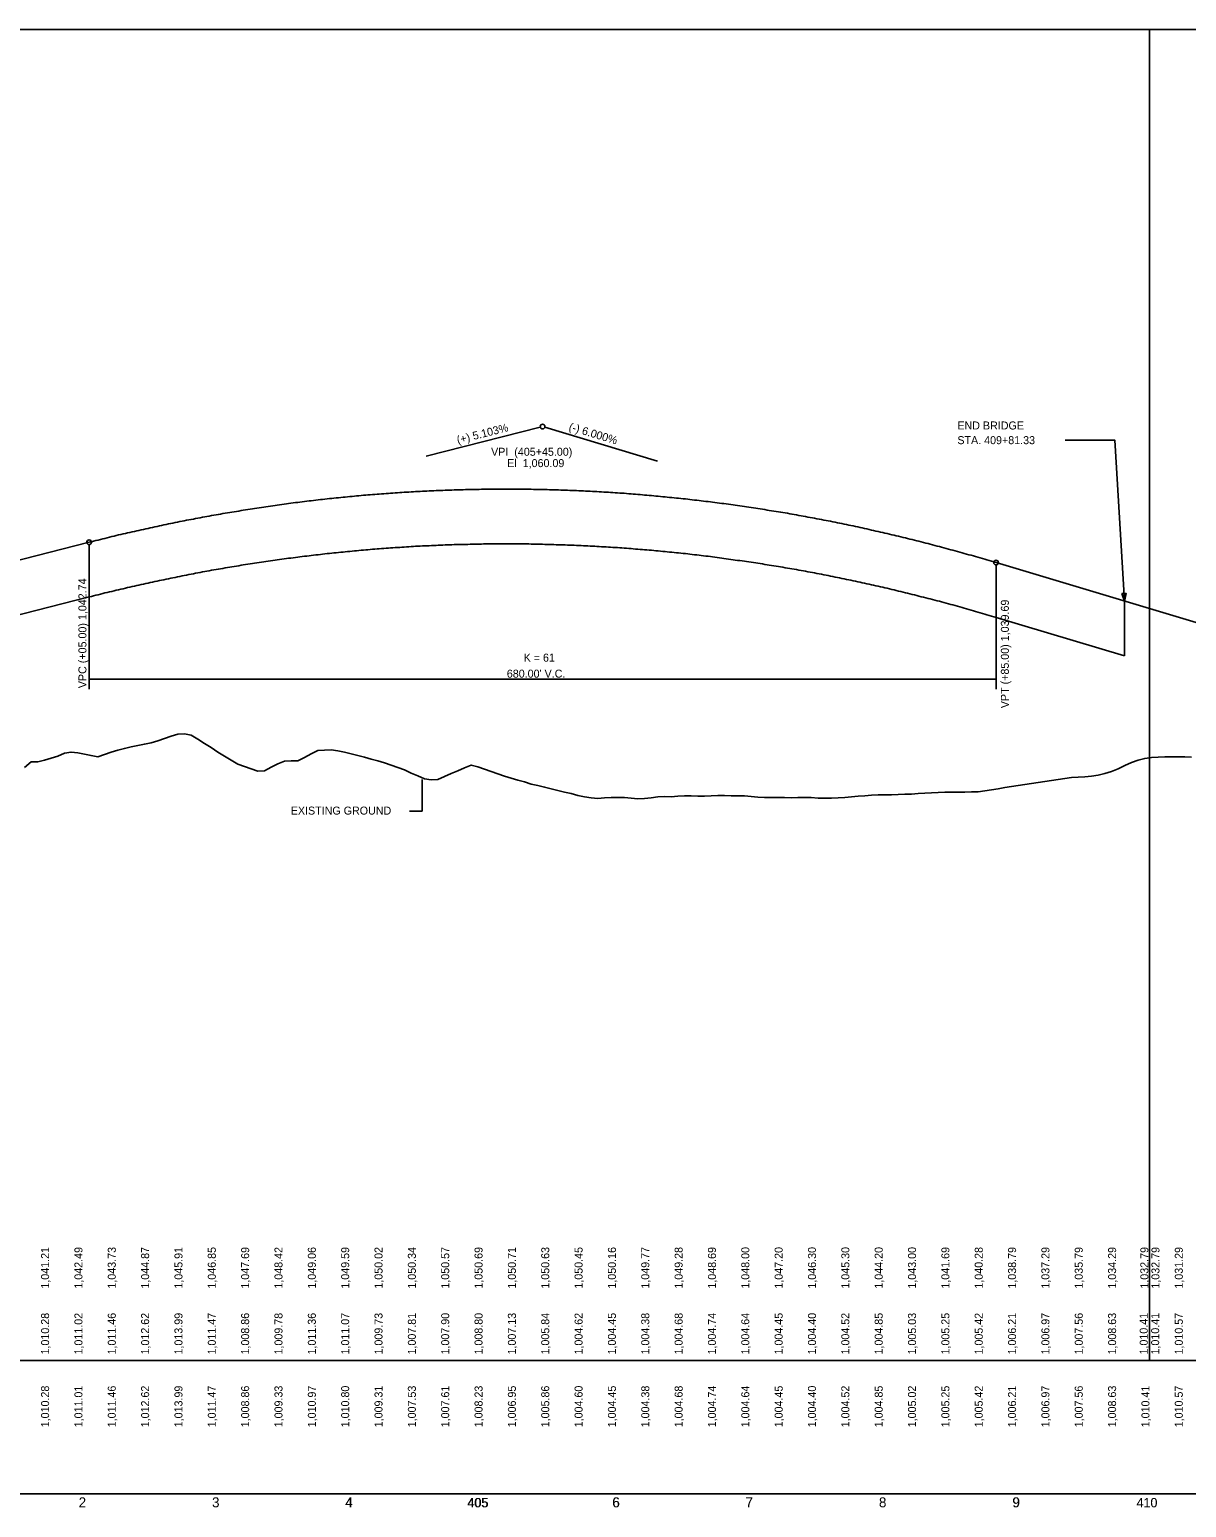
# Model space of a CAD drawing. Extents: x 150 to 16976893, y 3102 to 12559827.
# Drawn here: x 16974553 to 16975421, y 12558429 to 12559538 of the extents above; entities that cross this region are included whole.
import ezdxf

# ---------------------------------------------------------------- set-up
doc = ezdxf.new("R2010")
doc.units = 0
for name, color, linetype in [('Default', 7, 'Continuous'), ('Level 56', 7, 'Continuous'), ('RD_DDB_Ex_Tx', 7, 'Continuous'), ('RD_DDB_GradeTX', 7, 'Continuous'), ('RD_DDB_PI', 7, 'Continuous'), ('RD_DDB_Profile_EX', 7, 'Continuous'), ('RD_DDB_StaTX', 7, 'Continuous'), ('RD_DDB_StripGrade_EX', 7, 'Continuous'), ('RD_GPK_Profile_Cell', 7, 'Continuous'), ('RD_HC_TX_Sta20', 7, 'Continuous'), ('RD_PD_Bridge', 7, 'Continuous'), ('RD_PD_PatLn_I85', 7, 'Continuous'), ('RD_XS_Misc_Line', 7, 'Continuous')]:
    doc.layers.add(name, color=color, linetype=linetype)

msp = doc.modelspace()

# ---------------------------------------------------------------- linework, layer by layer
at = {"layer": 'Default'}
for points in [[(16973892.9, 12558539.3), (16975392.9, 12558539.3), (16975392.9, 12559537.5), (16973892.9, 12559537.5)], [(16975392.9, 12558539.3), (16976892.9, 12558539.3), (16976892.9, 12559537.5), (16975392.9, 12559537.5)]]:
    msp.add_lwpolyline(points, close=True, dxfattribs=at)
at = {"layer": 'RD_DDB_Ex_Tx'}
for p, q in [((16974847.7, 12558951.3), (16974847.7, 12558975.2)), ((16974838, 12558951.3), (16974847.7, 12558951.3))]:
    msp.add_line(p, q, dxfattribs=at)
at = {"layer": 'RD_DDB_PI'}
for p, q in [((16974850.7, 12559217.5), (16974936.2, 12559239.3)), ((16975024.1, 12559213.9), (16974939.6, 12559239.3))]:
    msp.add_line(p, q, dxfattribs=at)
msp.add_circle((16974937.9, 12559239.8), 1.75, dxfattribs=at)
at = {"layer": 'RD_DDB_Profile_EX'}
for points in [[(16974549.4, 12558984.1), (16974554.4, 12558988.4), (16974559.4, 12558988.3), (16974564.4, 12558989.7), (16974569.4, 12558991.1), (16974574.4, 12558992.7), (16974579.4, 12558994.8), (16974584.4, 12558995.7), (16974589.4, 12558995), (16974594.4, 12558994.2), (16974599.4, 12558993.1), (16974604.4, 12558992.2), (16974609.4, 12558993.9), (16974614.4, 12558995.6), (16974619.4, 12558997), (16974624.4, 12558998.4), (16974629.4, 12558999.5), (16974634.4, 12559000.6), (16974639.4, 12559001.7), (16974644.4, 12559002.7), (16974649.4, 12559004.2), (16974654.4, 12559005.9), (16974659.4, 12559007.6), (16974664.4, 12559009.1), (16974669.4, 12559009.3), (16974674.4, 12559008.3), (16974679.4, 12559005.4), (16974684.4, 12559002.2), (16974689.4, 12558999), (16974694.4, 12558995.7), (16974699.4, 12558992.6), (16974704.4, 12558989.5), (16974709.4, 12558986.5), (16974714.4, 12558984.9), (16974719.4, 12558983.1), (16974724.4, 12558981.4), (16974729.4, 12558981.7), (16974734.4, 12558984.3), (16974739.4, 12558986.8), (16974744.4, 12558988.8), (16974749.4, 12558989), (16974754.4, 12558989), (16974759.4, 12558991.6)], [(16974759.4, 12558991.6), (16974764.4, 12558994.3), (16974769.4, 12558996.8), (16974774.4, 12558997.2), (16974779.4, 12558997.3), (16974784.4, 12558996.6), (16974789.4, 12558995.5), (16974794.4, 12558994.3), (16974799.4, 12558993.1), (16974804.4, 12558991.8), (16974809.4, 12558990.4), (16974814.4, 12558989), (16974819.4, 12558987.5), (16974824.4, 12558985.8), (16974829.4, 12558984.2), (16974834.4, 12558982.4), (16974839.4, 12558979.8), (16974844.4, 12558977.8), (16974849.4, 12558975.7), (16974854.4, 12558974.8), (16974859.4, 12558975.1), (16974864.4, 12558977.3), (16974869.4, 12558979.5), (16974874.4, 12558981.6), (16974879.4, 12558983.8), (16974884.4, 12558985.9), (16974889.4, 12558984.5), (16974894.4, 12558982.8), (16974899.4, 12558981.1), (16974904.4, 12558979.4), (16974909.4, 12558977.7), (16974914.4, 12558976), (16974919.4, 12558974.5), (16974924.4, 12558973.3), (16974929.4, 12558971.5), (16974934.4, 12558970.5), (16974939.4, 12558969.4), (16974944.4, 12558968.1), (16974949.4, 12558966.9), (16974954.4, 12558965.7), (16974959.4, 12558964.5), (16974964.4, 12558963.1), (16974969.4, 12558962.1), (16974974.4, 12558961.4), (16974979.4, 12558960.9), (16974984.4, 12558961.3), (16974989.4, 12558961.6), (16974994.4, 12558961.5), (16974999.4, 12558961.6), (16975004.4, 12558961), (16975009.4, 12558960.7), (16975014.4, 12558960.9), (16975019.4, 12558961.3), (16975024.4, 12558962), (16975029.4, 12558962.4), (16975034.4, 12558962.2), (16975039.4, 12558962.5), (16975044.4, 12558962.8), (16975049.4, 12558962.8), (16975054.4, 12558962.6), (16975059.4, 12558962.6), (16975064.4, 12558962.8), (16975069.4, 12558963.1), (16975074.4, 12558963), (16975079.4, 12558962.9), (16975084.4, 12558962.9), (16975089.4, 12558962.8), (16975094.4, 12558962.4), (16975099.4, 12558961.9), (16975104.4, 12558961.6), (16975109.4, 12558961.6), (16975114.4, 12558961.7), (16975119.4, 12558961.5), (16975124.4, 12558961.4), (16975129.4, 12558961.5), (16975134.4, 12558961.6), (16975139.4, 12558961.5), (16975144.4, 12558961.2), (16975149.4, 12558961), (16975154.4, 12558961.1), (16975159.4, 12558961.3), (16975164.4, 12558961.6), (16975169.4, 12558962), (16975174.4, 12558962.5), (16975179.4, 12558962.9), (16975184.4, 12558963.3), (16975189.4, 12558963.6), (16975194.4, 12558963.6), (16975199.4, 12558963.5), (16975204.4, 12558963.8), (16975209.4, 12558964.1), (16975214.4, 12558964.2), (16975219.4, 12558964.5), (16975224.4, 12558964.8), (16975229.4, 12558965.1), (16975234.4, 12558965.3), (16975239.4, 12558965.5), (16975244.4, 12558965.6), (16975249.4, 12558965.7), (16975254.4, 12558965.7), (16975259.4, 12558965.8)], [(16975259.4, 12558965.8), (16975264.4, 12558965.9), (16975269.4, 12558966.6), (16975274.4, 12558967.4), (16975279.4, 12558968.2), (16975284.4, 12558969), (16975289.4, 12558969.8), (16975294.4, 12558970.6), (16975299.4, 12558971.3), (16975304.4, 12558972.1), (16975309.4, 12558972.9), (16975314.4, 12558973.6), (16975319.4, 12558974.4), (16975324.4, 12558975.1), (16975329.4, 12558975.9), (16975334.4, 12558976.6), (16975339.4, 12558976.9), (16975344.4, 12558977.2), (16975349.4, 12558977.5), (16975354.4, 12558978.4), (16975359.4, 12558979.7), (16975364.4, 12558981.1), (16975369.4, 12558983.1), (16975374.4, 12558985.5), (16975379.4, 12558987.9), (16975384.4, 12558989.6), (16975389.4, 12558990.9), (16975394.4, 12558991.6), (16975399.4, 12558991.9), (16975404.4, 12558992.2), (16975409.4, 12558992.2), (16975414.4, 12558992.2), (16975419.4, 12558992.2), (16975424.4, 12558991.9)]]:
    msp.add_lwpolyline(points, dxfattribs=at)
at = {"layer": 'RD_GPK_Profile_Cell'}
msp.add_line((16972208.1, 12558439.3), (16976677.1, 12558439.3), dxfattribs=at)
at = {"layer": 'RD_HC_TX_Sta20'}
for p, q in [((16974597.9, 12559042.8), (16974597.9, 12559151.3)), ((16975277.9, 12559042.8), (16975277.9, 12559136)), ((16974597.9, 12559050.3), (16975277.9, 12559050.3))]:
    msp.add_line(p, q, dxfattribs=at)
for centre in [(16974597.9, 12559153), (16975277.9, 12559137.8)]:
    msp.add_circle(centre, 1.75, dxfattribs=at)
at = {"layer": 'RD_PD_Bridge'}
for p, q in [((16974437.9, 12559071.1), (16974597.9, 12559112)), ((16975374.2, 12559067.8), (16975374.2, 12559108.9)), ((16975277.9, 12559096.7), (16975374.2, 12559067.8))]:
    msp.add_line(p, q, dxfattribs=at)
msp.add_spline([(16974597.9, 12559112), (16974611.5, 12559115.4), (16974625.1, 12559118.6), (16974638.7, 12559121.7), (16974652.3, 12559124.6), (16974665.9, 12559127.4), (16974679.5, 12559130.1), (16974693.1, 12559132.6), (16974706.7, 12559134.9), (16974720.3, 12559137.1), (16974733.9, 12559139.1), (16974747.5, 12559141), (16974761.1, 12559142.7), (16974774.7, 12559144.3), (16974788.3, 12559145.7), (16974801.9, 12559147), (16974815.5, 12559148.2), (16974829.1, 12559149.1), (16974842.7, 12559150), (16974856.3, 12559150.6), (16974869.9, 12559151.2), (16974883.5, 12559151.5), (16974897.1, 12559151.8), (16974910.7, 12559151.8), (16974924.3, 12559151.8), (16974937.9, 12559151.5), (16974951.5, 12559151.1), (16974965.1, 12559150.6), (16974978.7, 12559149.9), (16974992.3, 12559149.1), (16975005.9, 12559148.1), (16975019.5, 12559147), (16975033.1, 12559145.7), (16975046.7, 12559144.3), (16975060.3, 12559142.7), (16975073.9, 12559140.9), (16975087.5, 12559139), (16975101.1, 12559137), (16975114.7, 12559134.8), (16975128.3, 12559132.5), (16975141.9, 12559130), (16975155.5, 12559127.3), (16975169.1, 12559124.5), (16975182.7, 12559121.6), (16975196.3, 12559118.5), (16975209.9, 12559115.2), (16975223.5, 12559111.8), (16975237.1, 12559108.3), (16975250.7, 12559104.6), (16975264.3, 12559100.7), (16975277.9, 12559096.7)], degree=3, dxfattribs=at)
at = {"layer": 'RD_PD_PatLn_I85'}
msp.add_lwpolyline([(16975329.8, 12559229.6), (16975366.9, 12559229.6), (16975374.2, 12559108.9)], dxfattribs=at)
msp.add_lwpolyline([(16975372.3, 12559114.6), (16975374.2, 12559108.9), (16975375.4, 12559114.7)], close=True, dxfattribs=at)
at = {"layer": 'RD_XS_Misc_Line'}
for p, q in [((16974437.9, 12559112.2), (16974597.9, 12559153)), ((16975277.9, 12559137.8), (16975697.9, 12559011.8))]:
    msp.add_line(p, q, dxfattribs=at)
msp.add_spline([(16974597.9, 12559153), (16974611.5, 12559156.4), (16974625.1, 12559159.7), (16974638.7, 12559162.7), (16974652.3, 12559165.7), (16974665.9, 12559168.5), (16974679.5, 12559171.1), (16974693.1, 12559173.6), (16974706.7, 12559175.9), (16974720.3, 12559178.1), (16974733.9, 12559180.2), (16974747.5, 12559182.1), (16974761.1, 12559183.8), (16974774.7, 12559185.4), (16974788.3, 12559186.8), (16974801.9, 12559188.1), (16974815.5, 12559189.2), (16974829.1, 12559190.2), (16974842.7, 12559191), (16974856.3, 12559191.7), (16974869.9, 12559192.2), (16974883.5, 12559192.6), (16974897.1, 12559192.8), (16974910.7, 12559192.9), (16974924.3, 12559192.8), (16974937.9, 12559192.6), (16974951.5, 12559192.2), (16974965.1, 12559191.7), (16974978.7, 12559191), (16974992.3, 12559190.2), (16975005.9, 12559189.2), (16975019.5, 12559188), (16975033.1, 12559186.7), (16975046.7, 12559185.3), (16975060.3, 12559183.7), (16975073.9, 12559182), (16975087.5, 12559180.1), (16975101.1, 12559178), (16975114.7, 12559175.9), (16975128.3, 12559173.5), (16975141.9, 12559171), (16975155.5, 12559168.4), (16975169.1, 12559165.6), (16975182.7, 12559162.6), (16975196.3, 12559159.5), (16975209.9, 12559156.3), (16975223.5, 12559152.9), (16975237.1, 12559149.3), (16975250.7, 12559145.6), (16975264.3, 12559141.8), (16975277.9, 12559137.8)], degree=3, dxfattribs=at)

# ---------------------------------------------------------------- texts
at = {"layer": 'Level 56'}
for s, p in [('1,041.21', (16974567.9, 12558593.3)), ('1,042.49', (16974592.9, 12558593.3)), ('1,043.73', (16974617.9, 12558593.3)), ('1,044.87', (16974642.9, 12558593.3)), ('1,045.91', (16974667.9, 12558593.3)), ('1,046.85', (16974692.9, 12558593.3)), ('1,047.69', (16974717.9, 12558593.3)), ('1,048.42', (16974742.9, 12558593.3)), ('1,049.06', (16974767.9, 12558593.3)), ('1,049.59', (16974792.9, 12558593.3)), ('1,050.02', (16974817.9, 12558593.3)), ('1,050.34', (16974842.9, 12558593.3)), ('1,050.57', (16974867.9, 12558593.3)), ('1,050.69', (16974892.9, 12558593.3)), ('1,050.71', (16974917.9, 12558593.3)), ('1,050.63', (16974942.9, 12558593.3)), ('1,050.45', (16974967.9, 12558593.3)), ('1,050.16', (16974992.9, 12558593.3)), ('1,049.77', (16975017.9, 12558593.3)), ('1,049.28', (16975042.9, 12558593.3)), ('1,048.69', (16975067.9, 12558593.3)), ('1,048.00', (16975092.9, 12558593.3)), ('1,047.20', (16975117.9, 12558593.3)), ('1,046.30', (16975142.9, 12558593.3)), ('1,045.30', (16975167.9, 12558593.3)), ('1,044.20', (16975192.9, 12558593.3)), ('1,043.00', (16975217.9, 12558593.3)), ('1,041.69', (16975242.9, 12558593.3)), ('1,040.28', (16975267.9, 12558593.3)), ('1,038.79', (16975292.9, 12558593.3)), ('1,037.29', (16975317.9, 12558593.3)), ('1,035.79', (16975342.9, 12558593.3)), ('1,034.29', (16975367.9, 12558593.3)), ('1,032.79', (16975392.1, 12558593.3)), ('1,032.79', (16975400.4, 12558593.3)), ('1,031.29', (16975417.9, 12558593.3)), ('1,010.28', (16974567.9, 12558489.3)), ('1,011.01', (16974592.9, 12558489.3)), ('1,011.46', (16974617.9, 12558489.3)), ('1,012.62', (16974642.9, 12558489.3)), ('1,013.99', (16974667.9, 12558489.3)), ('1,011.47', (16974692.9, 12558489.3)), ('1,008.86', (16974717.9, 12558489.3)), ('1,009.33', (16974742.9, 12558489.3)), ('1,010.97', (16974767.9, 12558489.3)), ('1,010.80', (16974792.9, 12558489.3)), ('1,009.31', (16974817.9, 12558489.3)), ('1,007.53', (16974842.9, 12558489.3)), ('1,007.61', (16974867.9, 12558489.3)), ('1,008.23', (16974892.9, 12558489.3)), ('1,006.95', (16974917.9, 12558489.3)), ('1,005.86', (16974942.9, 12558489.3)), ('1,004.60', (16974967.9, 12558489.3)), ('1,004.45', (16974992.9, 12558489.3)), ('1,004.38', (16975017.9, 12558489.3)), ('1,004.68', (16975042.9, 12558489.3)), ('1,004.74', (16975067.9, 12558489.3)), ('1,004.64', (16975092.9, 12558489.3)), ('1,004.45', (16975117.9, 12558489.3)), ('1,004.40', (16975142.9, 12558489.3)), ('1,004.52', (16975167.9, 12558489.3)), ('1,004.85', (16975192.9, 12558489.3)), ('1,005.02', (16975217.9, 12558489.3)), ('1,005.25', (16975242.9, 12558489.3)), ('1,005.42', (16975267.9, 12558489.3)), ('1,006.21', (16975292.9, 12558489.3)), ('1,006.97', (16975317.9, 12558489.3)), ('1,007.56', (16975342.9, 12558489.3)), ('1,008.63', (16975367.9, 12558489.3)), ('1,010.41', (16975392.9, 12558489.3)), ('1,010.57', (16975417.9, 12558489.3))]:
    msp.add_text(s, height=6, rotation=90, dxfattribs=at).set_placement(p)
at = {"layer": 'RD_DDB_Ex_Tx'}
msp.add_text('EXISTING GROUND', height=6, dxfattribs=at).set_placement((16974749.1, 12558948.8))
at = {"layer": 'RD_DDB_GradeTX'}
for s, rotation, p in [('(+) 5.103%', 14.3136, (16974874.4, 12559226.7)), ('(-) 6.000%', 343.3008, (16974957.1, 12559237.1))]:
    msp.add_text(s, height=6, rotation=rotation, dxfattribs=at).set_placement(p)
at = {"layer": 'RD_DDB_PI'}
for s, p in [('VPI  (405+45.00)', (16974899.3, 12559217.9)), ('El  1,060.09', (16974911.4, 12559209.4))]:
    msp.add_text(s, height=6, dxfattribs=at).set_placement(p)
at = {"layer": 'RD_DDB_StaTX'}
for s, height, p in [('2', 7.5, (16974590.1, 12558429.3)), ('2', 7.5, (16974590.1, 12558429.3)), ('3', 7.5, (16974690.1, 12558429.3)), ('3', 7.5, (16974690.1, 12558429.3)), ('4', 7.5, (16974789.9, 12558429.3)), ('4', 7.5, (16974790.1, 12558429.3)), ('405', 7, (16974881.4, 12558429.3)), ('405', 7, (16974881.8, 12558429.3)), ('6', 7.5, (16974990.1, 12558429.3)), ('6', 7.5, (16974990.3, 12558429.3)), ('7', 7.5, (16975090, 12558429.3)), ('7', 7.5, (16975090.1, 12558429.3)), ('8', 7.5, (16975190.1, 12558429.3)), ('8', 7.5, (16975190.1, 12558429.3)), ('9', 7.5, (16975290.1, 12558429.3)), ('9', 7.5, (16975290.3, 12558429.3)), ('410', 7, (16975383.2, 12558429.3)), ('410', 7, (16975383.3, 12558429.3))]:
    msp.add_text(s, height=height, dxfattribs=at).set_placement(p)
at = {"layer": 'RD_DDB_StripGrade_EX'}
for s, p in [('1,010.28', (16974567.9, 12558543.9)), ('1,011.02', (16974592.9, 12558543.9)), ('1,011.46', (16974617.9, 12558543.9)), ('1,012.62', (16974642.9, 12558543.9)), ('1,013.99', (16974667.9, 12558543.9)), ('1,011.47', (16974692.9, 12558543.9)), ('1,008.86', (16974717.9, 12558543.9)), ('1,009.78', (16974742.9, 12558543.9)), ('1,011.36', (16974767.9, 12558543.9)), ('1,011.07', (16974792.9, 12558543.9)), ('1,009.73', (16974817.9, 12558543.9)), ('1,007.81', (16974842.9, 12558543.9)), ('1,007.90', (16974867.9, 12558543.9)), ('1,008.80', (16974892.9, 12558543.9)), ('1,007.13', (16974917.9, 12558543.9)), ('1,005.84', (16974942.9, 12558543.9)), ('1,004.62', (16974967.9, 12558543.9)), ('1,004.45', (16974992.9, 12558543.9)), ('1,004.38', (16975017.9, 12558543.9)), ('1,004.68', (16975042.9, 12558543.9)), ('1,004.74', (16975067.9, 12558543.9)), ('1,004.64', (16975092.9, 12558543.9)), ('1,004.45', (16975117.9, 12558543.9)), ('1,004.40', (16975142.9, 12558543.9)), ('1,004.52', (16975167.9, 12558543.9)), ('1,004.85', (16975192.9, 12558543.9)), ('1,005.03', (16975217.9, 12558543.9)), ('1,005.25', (16975242.9, 12558543.9)), ('1,005.42', (16975267.9, 12558543.9)), ('1,006.21', (16975292.9, 12558543.9)), ('1,006.97', (16975317.9, 12558543.9)), ('1,007.56', (16975342.9, 12558543.9)), ('1,008.63', (16975367.9, 12558543.9)), ('1,010.41', (16975391.6, 12558543.9)), ('1,010.41', (16975400.2, 12558543.9)), ('1,010.57', (16975417.9, 12558543.9))]:
    msp.add_text(s, height=6, rotation=90, dxfattribs=at).set_placement(p)
at = {"layer": 'RD_HC_TX_Sta20'}
for s, p in [('VPC (+05.00) 1,042.74', (16974595.9, 12559043.6)), ('VPT (+85.00) 1,039.69', (16975287.5, 12559028.6))]:
    msp.add_text(s, height=6, rotation=90, dxfattribs=at).set_placement(p)
for s, p in [('K = 61', (16974923.7, 12559063.5)), ("680.00' V.C.", (16974911.1, 12559051.5))]:
    msp.add_text(s, height=6, dxfattribs=at).set_placement(p)
at = {"layer": 'RD_PD_PatLn_I85'}
for s, p in [('END BRIDGE', (16975248.9, 12559237.6)), ('STA. 409+81.33', (16975248.9, 12559226.6))]:
    msp.add_text(s, height=6, rotation=360, dxfattribs=at).set_placement(p)

doc.saveas('drawing.dxf')
